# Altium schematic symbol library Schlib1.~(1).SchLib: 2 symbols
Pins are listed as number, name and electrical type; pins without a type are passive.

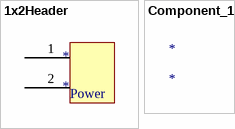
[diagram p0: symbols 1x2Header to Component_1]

## 1x2Header
designator *
pins: 1, 2 1

## Component_1
designator *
